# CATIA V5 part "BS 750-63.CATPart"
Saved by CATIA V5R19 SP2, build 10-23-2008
Part number: BS 750-63
Bounding box of the stored display mesh (mm): x -22.494 to 22.494, y -22.494 to 22.494, z 0 to 158
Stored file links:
  C:\Users\Bora\Desktop\3D Katı model\BS serisi\BS 750\BS 750-63.CATPart
  C:\Program Files\Dassault Systemes\B19\intel_a\reffiles\standard\MetricThickPitch.txt
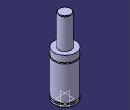
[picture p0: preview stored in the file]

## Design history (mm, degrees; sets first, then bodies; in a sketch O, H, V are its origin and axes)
Body1 (main body)
  Sketch1 on yz-plane, origin (0, 0, 0), H (0, 1, 0), V (0, 0, 1)
    point P3 (12.5, 157)
    point P5 (12.5, 157)
    point P7 (22.5, 80.5)
    point P8 (22.5, 78.5)
    point P12 (22.5, 78.5)
    point P13 (22.5, 80.5)
    line L1 (22.5, 0) -> (22.5, 4)
    line L2 (12.5, 157) -> (12.5, 94)
    arc A1 centre (11.5, 157) radius 1 from (12.5, 157) to (11.5, 158) ccw
    arc A2 centre (22.5, 79.5) radius 1 from (22.5, 80.5) to (22.5, 78.5) ccw
    line L3 (20, 7.5) -> (20, 4)
    line L4 (22.5, 7.5) -> (22.5, 78.5)
    line L5 (22.5, 80.5) -> (22.5, 94)
    line L6 (11.5, 158) -> (0, 158)
    point P15 (0, 158)
    line L7 (12.5, 94) -> (22.5, 94)
    line L8 (0, 0) -> (22.5, 0)
    line L9 (20, 7.5) -> (22.5, 7.5)
    line L10 (20, 4) -> (22.5, 4)
    coincidence: P15 V, P3 P5, P7 P13, P8 P12
    tangency: L6 A1
    horizontal: L7 H, L8 H, L9 H, L10 H
  Shaft1: profile Sketch1, axis Sketch1.V, angle 360
  Sketch2 on face of Shaft1 from Sketch1.L8, origin (0, 0, 0), H (1, 0, 0), V (0, -1, 0)
    point P1 (10, 0)
    distance P1 V = 10
  Hole1: placed by Sketch2, at (10, 0, 0) direction (0, 0, 1), diameter 6.647, depth 4, threaded "M8", thread diameter 8, thread depth 4, pitch 1.25
  CircPattern1: of Hole1, instances 2, angular step 180, axis from xy-plane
